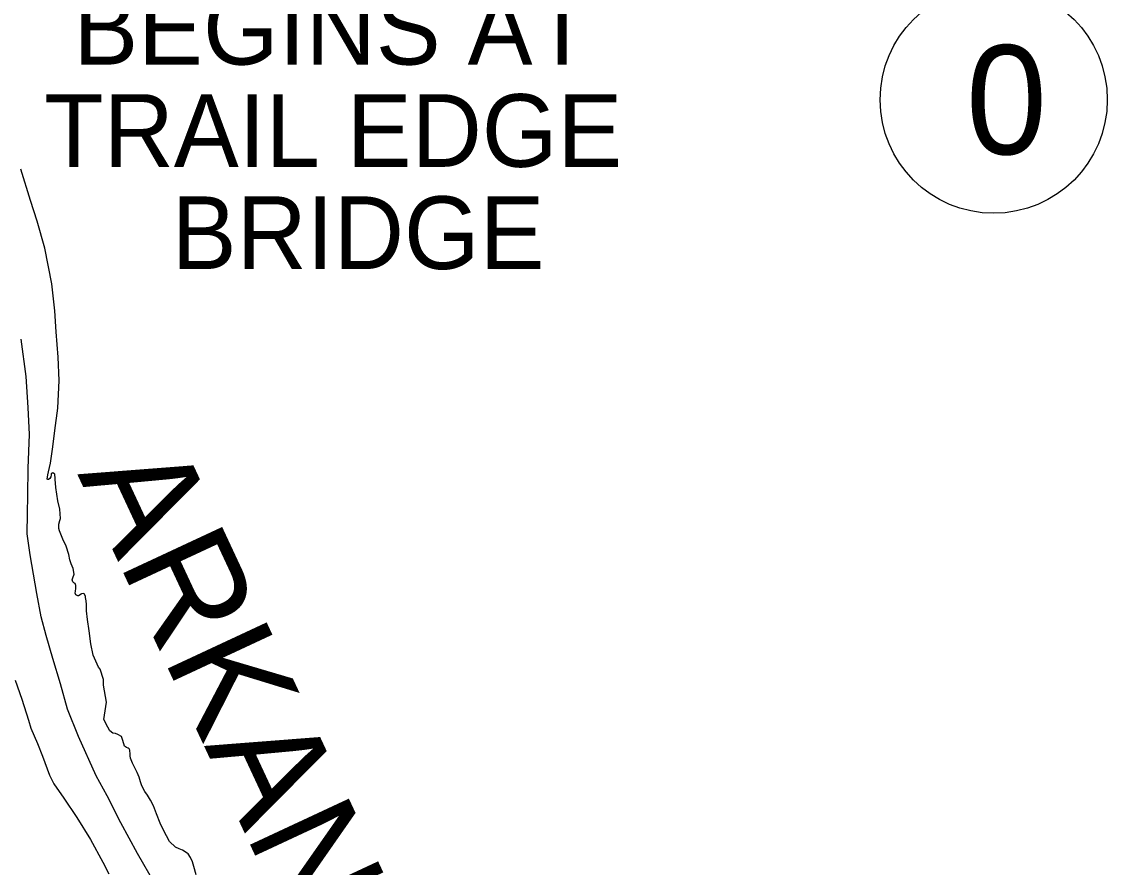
# Model space of a CAD drawing. Extents: x -83719 to 153526, y -11835 to 11446.
# Drawn here: x -1976.1 to -1765.8, y 623.4 to 787.2 of the extents above; entities that cross this region are included whole.
import ezdxf

# ---------------------------------------------------------------- set-up
doc = ezdxf.new("R2010")
doc.units = 0
for name, color, linetype in [('Level 2', 7, 'Continuous'), ('Level 25', 7, 'Continuous'), ('Level 27', 7, 'Continuous'), ('Level 9', 7, 'Continuous')]:
    doc.layers.add(name, color=color, linetype=linetype)

msp = doc.modelspace()

# ---------------------------------------------------------------- linework, layer by layer
at = {"layer": 'Level 2'}
msp.add_lwpolyline([(-1950.22, 620.15), (-1953.66, 626.09), (-1956.88, 632), (-1959.53, 637.23), (-1961.63, 641.09), (-1965.03, 648.76), (-1967.18, 654.02), (-1968.57, 658.94), (-1970.03, 663.87), (-1971.32, 668.32), (-1972.29, 671.93), (-1973.15, 676.45), (-1974.39, 683.94), (-1974.99, 687.99), (-1974.96, 691.96), (-1974.86, 695.4), (-1974.82, 700.74), (-1974.57, 707.25), (-1974.83, 712.5), (-1975.18, 718.48), (-1976.15, 725.74)], dxfattribs=at)
msp.add_lwpolyline([(-1950.22, 620.15), (-1953.66, 626.09), (-1956.88, 632), (-1959.53, 637.23), (-1961.63, 641.09), (-1965.03, 648.76), (-1967.18, 654.02), (-1968.57, 658.94), (-1970.03, 663.87), (-1971.32, 668.32), (-1972.29, 671.93), (-1973.15, 676.45), (-1974.39, 683.94), (-1974.99, 687.99), (-1974.96, 691.96), (-1974.86, 695.4), (-1974.82, 700.74), (-1974.57, 707.25), (-1974.83, 712.5), (-1975.18, 718.48), (-1976.15, 725.74)], dxfattribs=at)
at = {"layer": 'Level 27'}
msp.add_circle((-1787.8, 772.1), 22, dxfattribs=at)
at = {"layer": 'Level 9'}
for points in [[(-1966.25, 679.07), (-1966.18, 679.47), (-1965.87, 680.2), (-1966.09, 681.3), (-1966.45, 682.17), (-1966.71, 682.98), (-1966.94, 684.01), (-1967.42, 685.59), (-1968.08, 686.96), (-1968.76, 688.6), (-1968.89, 689.01), (-1968.89, 689.11), (-1968.89, 689.87), (-1968.65, 690.57), (-1968.55, 690.94), (-1968.66, 692.78), (-1969.05, 694.39), (-1969.43, 696.96), (-1969.55, 698.6), (-1969.58, 698.96), (-1969.61, 699.3), (-1969.67, 699.57), (-1969.81, 699.7), (-1970, 699.8), (-1970.37, 699.64), (-1970.37, 699.41), (-1970.41, 699.07), (-1970.58, 698.74), (-1970.85, 698.51), (-1970.98, 698.51), (-1971.11, 698.58), (-1971.01, 699.44), (-1970.87, 700.01), (-1970.49, 701.71), (-1970.03, 704.88), (-1969.64, 708.05), (-1969.07, 712.35), (-1968.8, 717.7), (-1968.99, 722.24), (-1969.35, 727.15), (-1969.65, 731.2), (-1970.24, 736.41), (-1971.58, 743.37), (-1973.04, 748.56), (-1974.34, 752.58), (-1976.25, 758.64)], [(-1966.25, 679.07), (-1966.18, 679.47), (-1965.87, 680.2), (-1966.09, 681.3), (-1966.45, 682.17), (-1966.71, 682.98), (-1966.94, 684.01), (-1967.42, 685.59), (-1968.08, 686.96), (-1968.76, 688.6), (-1968.89, 689.01), (-1968.89, 689.11), (-1968.89, 689.87), (-1968.65, 690.57), (-1968.55, 690.94), (-1968.66, 692.78), (-1969.05, 694.39), (-1969.43, 696.96), (-1969.55, 698.6), (-1969.58, 698.96), (-1969.61, 699.3), (-1969.67, 699.57), (-1969.81, 699.7), (-1970, 699.8), (-1970.37, 699.64), (-1970.37, 699.41), (-1970.41, 699.07), (-1970.58, 698.74), (-1970.85, 698.51), (-1970.98, 698.51), (-1971.11, 698.58), (-1971.01, 699.44), (-1970.87, 700.01), (-1970.49, 701.71), (-1970.03, 704.88), (-1969.64, 708.05), (-1969.07, 712.35), (-1968.8, 717.7), (-1968.99, 722.24), (-1969.35, 727.15), (-1969.65, 731.2), (-1970.24, 736.41), (-1971.58, 743.37), (-1973.04, 748.56), (-1974.34, 752.58), (-1976.25, 758.64)], [(-1942.28, 621.96), (-1942.7, 623.57), (-1942.99, 624.47), (-1943.39, 625.28), (-1943.81, 626.01), (-1944.01, 626.12), (-1944.94, 626.69), (-1945.57, 627), (-1946.3, 627.3), (-1947.45, 628.42), (-1948.6, 630.6), (-1949.22, 631.94), (-1949.94, 633.78), (-1950.56, 635.32), (-1951.08, 636.43), (-1951.67, 637.4), (-1952.2, 638.11), (-1952.79, 639.21), (-1953.05, 639.98), (-1953.31, 640.85), (-1953.67, 641.79), (-1954.06, 642.56), (-1954.62, 643.57), (-1955.01, 644.57), (-1955.04, 644.98), (-1955.04, 645.14), (-1955.07, 645.51), (-1955.1, 645.91), (-1955.13, 646.08), (-1955.26, 646.35), (-1955.46, 646.48), (-1955.73, 646.58), (-1956.12, 646.89), (-1956.48, 647.96), (-1956.64, 648.56), (-1956.74, 648.73), (-1957.44, 649.1), (-1957.9, 649.34), (-1958.43, 649.38), (-1958.96, 649.85), (-1959.39, 650.55), (-1960.14, 652.06), (-1959.65, 655.4), (-1960.22, 658.68), (-1960.24, 659.81), (-1960.89, 661.76), (-1961.16, 662.16), (-1962.2, 664.47), (-1962.68, 666.71), (-1963, 669.22), (-1963.31, 671.39), (-1963.5, 673.07), (-1963.53, 673.83), (-1963.52, 674.33), (-1963.55, 675.04), (-1963.68, 675.67), (-1963.71, 675.94), (-1963.97, 676.38), (-1964.1, 676.41), (-1964.47, 676.38), (-1964.57, 676.28), (-1965.04, 676.02), (-1965.21, 675.98), (-1965.54, 676.19), (-1965.67, 676.49), (-1965.63, 676.89), (-1965.56, 677.39), (-1965.56, 677.72), (-1965.55, 678.02), (-1965.72, 678.36), (-1965.95, 678.53), (-1966.18, 678.73), (-1966.21, 678.87), (-1966.25, 679.07)], [(-1942.28, 621.96), (-1942.7, 623.57), (-1942.99, 624.47), (-1943.39, 625.28), (-1943.81, 626.01), (-1944.01, 626.12), (-1944.94, 626.69), (-1945.57, 627), (-1946.3, 627.3), (-1947.45, 628.42), (-1948.6, 630.6), (-1949.22, 631.94), (-1949.94, 633.78), (-1950.56, 635.32), (-1951.08, 636.43), (-1951.67, 637.4), (-1952.2, 638.11), (-1952.79, 639.21), (-1953.05, 639.98), (-1953.31, 640.85), (-1953.67, 641.79), (-1954.06, 642.56), (-1954.62, 643.57), (-1955.01, 644.57), (-1955.04, 644.98), (-1955.04, 645.14), (-1955.07, 645.51), (-1955.1, 645.91), (-1955.13, 646.08), (-1955.26, 646.35), (-1955.46, 646.48), (-1955.73, 646.58), (-1956.12, 646.89), (-1956.48, 647.96), (-1956.64, 648.56), (-1956.74, 648.73), (-1957.44, 649.1), (-1957.9, 649.34), (-1958.43, 649.38), (-1958.96, 649.85), (-1959.39, 650.55), (-1960.14, 652.06), (-1959.65, 655.4), (-1960.22, 658.68), (-1960.24, 659.81), (-1960.89, 661.76), (-1961.16, 662.16), (-1962.2, 664.47), (-1962.68, 666.71), (-1963, 669.22), (-1963.31, 671.39), (-1963.5, 673.07), (-1963.53, 673.83), (-1963.52, 674.33), (-1963.55, 675.04), (-1963.68, 675.67), (-1963.71, 675.94), (-1963.97, 676.38), (-1964.1, 676.41), (-1964.47, 676.38), (-1964.57, 676.28), (-1965.04, 676.02), (-1965.21, 675.98), (-1965.54, 676.19), (-1965.67, 676.49), (-1965.63, 676.89), (-1965.56, 677.39), (-1965.56, 677.72), (-1965.55, 678.02), (-1965.72, 678.36), (-1965.95, 678.53), (-1966.18, 678.73), (-1966.21, 678.87), (-1966.25, 679.07)], [(-1977.35, 659.68), (-1976.05, 655.97), (-1974.75, 651.88), (-1974.3, 650.34), (-1973.02, 647.36), (-1972.04, 644.91), (-1970.68, 641.23), (-1969.82, 639.55), (-1967.92, 636.8), (-1965.35, 633.03), (-1962.76, 628.77), (-1960.36, 624.41), (-1959.15, 622.13)], [(-1977.35, 659.68), (-1976.05, 655.97), (-1974.75, 651.88), (-1974.3, 650.34), (-1973.02, 647.36), (-1972.04, 644.91), (-1970.68, 641.23), (-1969.82, 639.55), (-1967.92, 636.8), (-1965.35, 633.03), (-1962.76, 628.77), (-1960.36, 624.41), (-1959.15, 622.13)]]:
    msp.add_lwpolyline(points, dxfattribs=at)

# ---------------------------------------------------------------- texts
at = {"layer": 'Level 25'}
for s, p in [('BEGINS AT', (-1966.06, 778.91)), ('TRAIL EDGE', (-1971.68, 759.1)), ('BRIDGE', (-1947, 739.3))]:
    msp.add_text(s, height=14.08, dxfattribs=at).set_placement(p)
at = {"layer": 'Level 27'}
msp.add_text('0', height=21.12, dxfattribs=at).set_placement((-1793.18, 761.54))
at = {"layer": 'Level 9'}
msp.add_text('ARKANSAS', height=21.12, rotation=295, dxfattribs=at).set_placement((-1965.31, 699.58))

doc.saveas('drawing.dxf')
